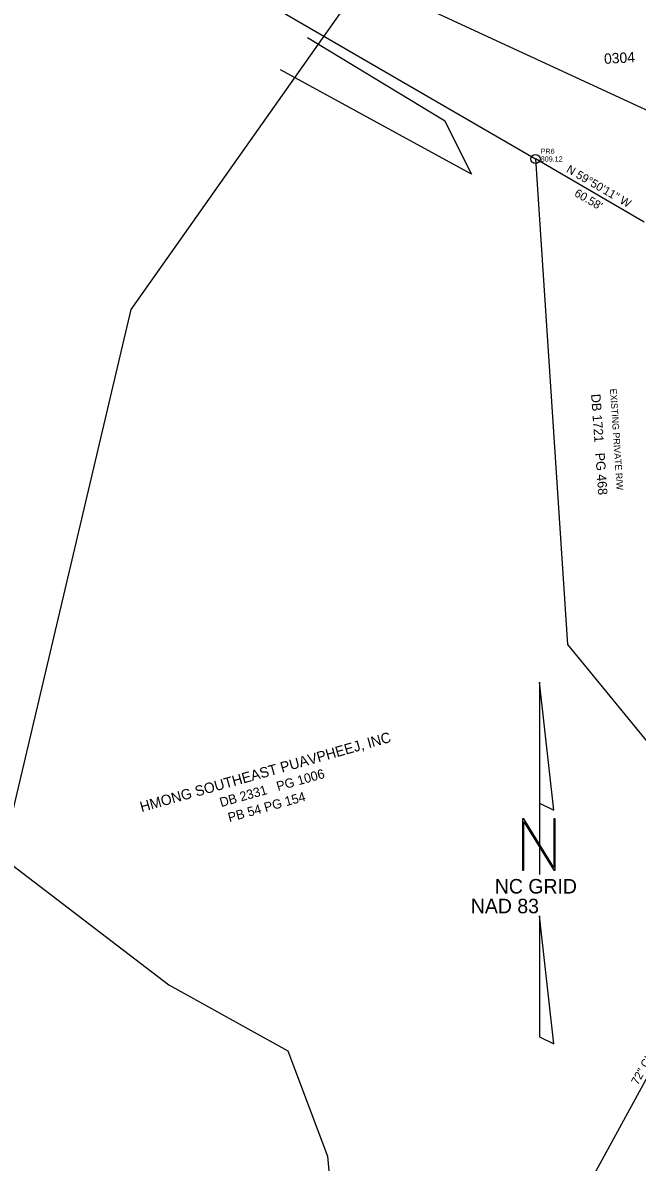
# Model space of a CAD drawing. Extents: x 1316460 to 1321645, y 684173 to 687077.
# Drawn here: x 1319126 to 1319422, y 685892 to 686441 of the extents above; entities that cross this region are included whole.
import ezdxf

# ---------------------------------------------------------------- set-up
doc = ezdxf.new("R2010")
doc.units = 0
for name, color, linetype in [('CTL North Arrow NAD 83 CELL', 7, 'Continuous'), ('Exist Hydrographic Confluence CELL', 7, 'Continuous'), ('Exist Hydrographic Confluence Cogo Elevation', 7, 'Continuous'), ('Exist Hydrographic Confluence Cogo Number', 7, 'Continuous'), ('Exist Other Culture Fence Line', 7, 'Continuous'), ('Exist Other Culture Fence Line Text', 7, 'Continuous'), ('Exist Property Deed Book Text', 7, 'Continuous'), ('Exist Property Line', 7, 'Continuous'), ('Exist Property Line Text', 7, 'Continuous'), ('Exist Property Owner Text', 7, 'Continuous'), ('Exist Right of Way Easement Line', 7, 'Continuous'), ('Exist Right of Way Easement Line Text', 7, 'Continuous'), ('Exist Vegetation Woods Line', 7, 'Continuous'), ('Old_Level_59', 7, 'Continuous')]:
    doc.layers.add(name, color=color, linetype=linetype)

# ---------------------------------------------------------------- blocks, each defined once
blk = doc.blocks.new('CTL NORTH ARROW NAD 83')
at = {"layer": 'CTL North Arrow NAD 83 CELL'}
for points in [[(0.001, 1.743), (0.001, 0.577), (0.139, 0.509)], [(-0.163, -0.068), (-0.149, -0.068), (-0.149, 0.399), (0.139, -0.068), (0.152, -0.068), (0.152, 0.426), (0.139, 0.426), (0.139, -0.041), (-0.149, 0.426), (-0.163, 0.426)], [(0.001, -1.673), (0.139, -1.742), (0.001, -0.507)]]:
    blk.add_lwpolyline(points, close=True, dxfattribs=at)
blk.add_lwpolyline([(0.001, 0.577), (0.001, -0.11)], dxfattribs=at)
for s, p in [('NC GRID', (-0.429, -0.293)), ('   NAD 83', (-0.816, -0.483))]:
    blk.add_text(s, height=0.14, dxfattribs=at).set_placement(p)

msp = doc.modelspace()

# ---------------------------------------------------------------- linework, layer by layer
at = {"layer": 'Exist Hydrographic Confluence CELL'}
for radius in [2.2, 2.2, 0.0707, 0.0707]:
    msp.add_circle((1319373.21, 686375.53), radius, dxfattribs=at)
at = {"layer": 'Exist Other Culture Fence Line'}
msp.add_lwpolyline([(1319427.35, 686158.29), (1319479.18, 686028.54), (1319390.78, 685866.77), (1319305.88, 685834.62)], dxfattribs=at)
at = {"layer": 'Exist Property Line'}
for p in [(1318848.79, 686680.3), (1319425.58, 686345.09)]:
    msp.add_line(p, (1319373.21, 686375.53), dxfattribs=at)
at = {"layer": 'Exist Right of Way Easement Line'}
for points in [[(1319373.21, 686375.53), (1319388.66, 686141.58)], [(1319388.66, 686141.58), (1319495.45, 686010.96)]]:
    msp.add_lwpolyline(points, dxfattribs=at)
at = {"layer": 'Exist Vegetation Woods Line'}
for points in [[(1319263.45, 686434.12), (1319329.31, 686394.08), (1319342.32, 686368.26), (1319250.38, 686418.53)], [(1319101.66, 686050.12), (1319196.68, 685977.46), (1319253.97, 685945.67), (1319273.05, 685894.99), (1319277.48, 685845.24), (1319293.25, 685787.57), (1319315.49, 685752.17), (1319325.45, 685719.52), (1319304.66, 685680.79), (1319280.1, 685652.84), (1319263.36, 685699.34), (1319226.4, 685692.01), (1319230.34, 685658.84), (1319255.19, 685632.07), (1319257.64, 685601.33), (1319222.54, 685537.37), (1319192.25, 685493.91), (1319186.21, 685519.16), (1319181.67, 685548.26), (1319160.36, 685570.48), (1319115.06, 685612.94), (1319148.78, 685654.33), (1319106.92, 685683.06)]]:
    msp.add_lwpolyline(points, dxfattribs=at)
at = {"layer": 'Old_Level_59'}
msp.add_lwpolyline([(1318697.3, 685264.68), (1318675.61, 685496.37), (1319013.72, 685603.72), (1319178.5, 686302.95), (1319290.7, 686462.26), (1319434.76, 686395.34), (1319426.96, 685366.75), (1319230.41, 685144.48), (1318730.33, 685054.78)], close=True, dxfattribs=at)

# ---------------------------------------------------------------- block references
at = {"layer": 'CTL North Arrow NAD 83 CELL', "xscale": 50, "yscale": 50}
msp.add_blockref('CTL NORTH ARROW NAD 83', (1319375.07, 686036.18), dxfattribs=at)

# ---------------------------------------------------------------- texts
at = {"layer": 'Exist Hydrographic Confluence Cogo Elevation'}
msp.add_text('809.12', height=2.5, dxfattribs=at).set_placement((1319375.71, 686374.28))
msp.add_text('809.12', height=2.5, dxfattribs=at).set_placement((1319375.71, 686374.28))
at = {"layer": 'Exist Hydrographic Confluence Cogo Number'}
msp.add_text('PR6', height=2.5, dxfattribs=at).set_placement((1319375.71, 686378.03))
msp.add_text('PR6', height=2.5, dxfattribs=at).set_placement((1319375.71, 686378.03))
at = {"layer": 'Exist Other Culture Fence Line Text'}
msp.add_text('72" CHL W/ 3SBW', height=4, rotation=61.3459, dxfattribs=at).set_placement((1319422.49, 685928.97))
at = {"layer": 'Exist Property Deed Book Text'}
for s, rotation, p in [('DB 1721   PG 468', 274.0957, (1319399.93, 686262.15)), ('DB 2331   PG 1006', 15.7349, (1319221.83, 686063.18)), ('PB 54 PG 154', 15.7349, (1319225.82, 686055.88))]:
    msp.add_text(s, height=4.5, rotation=rotation, dxfattribs=at).set_placement(p)
at = {"layer": 'Exist Property Line Text'}
for s, p in [('N 59%%D50\'11" W', (1319387.67, 686369.43)), ("60.58'", (1319391.55, 686357.93))]:
    msp.add_text(s, height=4, rotation=329.8365, dxfattribs=at).set_placement(p)
at = {"layer": 'Exist Property Owner Text'}
msp.add_text('HMONG SOUTHEAST PUAVPHEEJ, INC', height=5, rotation=15.7349, dxfattribs=at).set_placement((1319183.54, 686060.74))
at = {"layer": 'Exist Right of Way Easement Line Text'}
msp.add_text('EXISTING PRIVATE R/W', height=3.2, rotation=273.7797, dxfattribs=at).set_placement((1319409.04, 686264.74))
at = {"layer": 'Old_Level_59'}
msp.add_text('0304', height=5, rotation=3.1221, dxfattribs=at).set_placement((1319406.34, 686421.34))

doc.saveas('drawing.dxf')
